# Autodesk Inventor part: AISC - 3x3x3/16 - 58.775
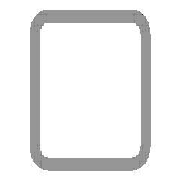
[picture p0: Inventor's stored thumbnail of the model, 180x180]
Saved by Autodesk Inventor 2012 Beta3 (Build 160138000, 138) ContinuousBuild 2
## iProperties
IsCustomPart: 1
_CCFamilyMember: 9
_CCFamilyDisplayName: ANSI AISC (Square) - Tube
_FrameMemberDoc: Frame Member File
_Version: 15.0.0
_GetPNFromCC: 1
Created: 2011-01
Part Number: AISC - 3x3x3/16 - 58.775
Material: Steel, Mild
Description: Tube
Document SubType Name: Modeling
Standard: ANSI
Designer: Beta-8540w
Standards Organization: ANSI
Language: en-US
Size Designation: 3x3x3/16
Categories: <MemberInstance><Categories><Category DisplayName="Structural Shapes" InternalName="089c4875-fa83-4c05-b084-43b9cc11f5ed" Mnemonic="GRDR"><CategoryParameter Dis
Stock Number: 3x3x3/16
Density: 7.86 g/cm^3
G_L: 58.775 in
G_W: 3.000 in
G_H: 3.000 in
+F1DD31D7-8EA7-4030-B73F-B4109CE49B1F+CUTDETAIL1: Cut
Author: Beta-8540w
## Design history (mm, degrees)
node "Start plane"
node "End plane"
sketch "Sketch"
  geometry: L1 (-38.1, -28.575)-(-38.1, 28.575); L2 (-28.575, 38.1)-(28.575, 38.1); L3 (38.1, 28.575)-(38.1, -28.575); L4 (28.575, -38.1)-(-28.575, -38.1); L5 (-28.575, 33.337)-(28.575, 33.338); L6 (33.338, 28.575)-(33.338, -28.575); L7 (28.575, -33.337)-(-28.575, -33.338); L8 (-33.338, -28.575)-(-33.338, 28.575); L9 (0, 56.102)-(0, -56.102) reference; L10 (-56.102, 0)-(56.102, 0) reference; A1 r 9.525 centre (-28.575, -28.575) between (-38.1, -28.575) and (-28.575, -38.1); A2 r 9.525 centre (-28.575, 28.575) between (-28.575, 38.1) and (-38.1, 28.575); A3 r 9.525 centre (28.575, 28.575) between (38.1, 28.575) and (28.575, 38.1); A4 r 9.525 centre (28.575, -28.575) between (28.575, -38.1) and (38.1, -28.575); A5 r 4.763 centre (-28.575, 28.575) between (-28.575, 33.337) and (-33.338, 28.575); A6 r 4.763 centre (28.575, 28.575) between (33.338, 28.575) and (28.575, 33.338); A7 r 4.763 centre (28.575, -28.575) between (28.575, -33.337) and (33.338, -28.575); A8 r 4.763 centre (-28.575, -28.575) between (-33.338, -28.575) and (-28.575, -33.338)
  constraints: 16 end point, 16 point on circle, 8 centre point, 8 tangent, 4 parallel, 3 equal radius, 2 perpendicular, 7 other
  dimensions: "d10" = 76.2 distance between parallel lines of L2 L4 (= G_H); "d11" = 76.2 distance between parallel lines of L1 L3 (= G_W); "d12" = 4.7625 distance between parallel lines of L3 L6 (= G_T); "d15" = 38.1 distance between parallel lines of L2 L10 (= 0.5 x d10); "d16" = 38.1 distance between parallel lines of L9 L3 (= 0.5 x d11); "d17" = 9.525 radius of A1 (= G_IR)
extrude "Body" new body sketch "Sketch" stored distance "d3" = 1492.89148 (= G_L); taper "d4" = 0 deg
node "Driven Length"
  sketch "Sketch3"
    geometry: L1 (0, 0)-(10, 0) reference
    constraints: 2 end point, 1 horizontal
  workplane "Work Plane3"
  sketch "Sketch4"
    geometry: L1 (-2, 31.109)-(12, 31.109) reference; L2 (-2, 1524)-(12, 1524) reference
    dimensions: "d19" = 1492.89148 distance between parallel lines of L1 L2 (derived)
workplane "Work Plane4"
split "Split1"
body "Solid1"
other parameters: "G_W" = 76.2 [user parameter; used in 1 equation term], "G_H" = 76.2 [user parameter; used in 1 equation term], "G_T" = 4.7625 [user parameter; used in 1 equation term], "G_IR" = 9.525 [user parameter; used in 1 equation term], "G_L" = 1492.89148 (= d19) [user parameter; used in 1 equation term], "G_OFFSET_START" = -31.10852 [user parameter; used in 1 equation term], "G_OFFSET_END" = 0 [user parameter; used in 1 equation term], "d13" = 31.10852 (= -G_OFFSET_START), "d14" = 1524 (= G_OFFSET_END + B_L), "B_L" = 1524 [user parameter; used in 1 equation term], "d18" = 90 deg
